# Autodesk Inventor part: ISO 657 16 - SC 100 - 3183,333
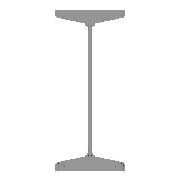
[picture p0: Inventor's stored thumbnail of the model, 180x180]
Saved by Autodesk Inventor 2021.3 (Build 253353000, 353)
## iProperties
IsCustomPart: 1
_CCFamilyMember: 1
_CCFamilyDisplayName: ISO 657/16 - 1980 - Poutres en acier laminées à chaud - Partie 16: profilés en H (série métrique) - Cotes et propriétés de section
_FrameMemberDoc: Frame Member File
_Version: 25.0.0
_GetPNFromCC: 1
Created: 2018-07
Part Number: ISO 657 16 - SC 100 - 3183,333
Material: Acier, doux
Description: Poutres en acier laminées à chaud - Partie 16: profilés en H (série métrique) - Cotes et propriétés de section
Document SubType Name: Modeling
Standard: ISO
Designer: Fabian Perrée
Standard Revision: First edition 1980-02-15
Standards Organization: ISO
Language: fr-FR
Size Designation: SC 100
Categories: <MemberInstance><Categories><Category DisplayName="Profilés" InternalName="089c4875-fa83-4c05-b084-43b9cc11f5ed" Mnemonic="GRDR"><CategoryParameter DisplayName=
Stock Number: SC 100
Density: 7.85 g/cm^3
Appearance: Semi-poli
Mass: 62799.5 g
Surface Area: 17060.8 cm^2
Volume: 7999.94 cm^3
G_W: 100,000 mm
G_H: 100,000 mm
+C8570A6E-3ADF-402B-AF4B-F69D73FB0D4A+DETAILDECOUPE1: Angle de coupe 67,38 deg
+12B5BAF0-3E22-4404-8C3D-A4FF2A8CEEA4+DETAILDECOUPE2: Angle de coupe 67,38 deg
G_L: 3183,333 mm
Author: Fabian Perrée
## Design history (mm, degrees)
node "Plan de départ"
node "Plan de fin"
sketch "Esquisse"
  geometry: L1 (-3, 0)-(-3, -26.266); L2 (-13.33, -38.149)-(-44.835, -42.577); L3 (-50, -48.518)-(-50, -50); L4 (-50, -50)-(0, -50); L5 (-26.5, -50)-(-26.5, -40); L6 (-61.333, 0)-(81.777, 0); L7 (0, 0)-(0, -50); L8 (0, -60)-(0, 80); L9 (3, 0)-(3, -26.266); L10 (13.33, -38.149)-(44.835, -42.577); L11 (50, -48.518)-(50, -50); L12 (50, -50)-(0, -50); L13 (-3, 0)-(0, 0); L14 (-3, 0)-(-3, 26.266); L15 (-13.33, 38.149)-(-44.835, 42.577); L16 (-50, 48.518)-(-50, 50); L17 (-50, 50)-(0, 50); L18 (50, 48.518)-(50, 50); L19 (13.33, 38.149)-(44.835, 42.577); L20 (3, 0)-(3, 26.266); L21 (50, 50)-(0, 50); L22 (0, 108)-(0, -88) reference; L23 (-89.955, 0)-(110.399, 0) reference; A1 r 6 centre (-44, 48.518) between (-50, 48.518) and (-44.835, 42.577); A2 r 6 centre (44, 48.518) between (44.835, 42.577) and (50, 48.518); A3 r 6 centre (44, -48.518) between (50, -48.518) and (44.835, -42.577); A4 r 6 centre (-44, -48.518) between (-44.835, -42.577) and (-50, -48.518); A5 r 12 centre (-15, 26.266) between (-3, 26.266) and (-13.33, 38.149); A6 r 12 centre (15, 26.266) between (13.33, 38.149) and (3, 26.266); A7 r 12 centre (15, -26.266) between (3, -26.266) and (13.33, -38.149); A8 r 12 centre (-15, -26.266) between (-13.33, -38.149) and (-3, -26.266); 14 further points
  constraints: 42 end point, 24 point on line, 17 symmetric about line, 16 point on circle, 16 tangent, 8 centre point, 6 equal radius, 4 collinear, 2 perpendicular, 12 other
  dimensions: "d1" = 10 vertical distance of L3.end L5.end (= G_T1); "d2" = 23.5 distance between parallel lines of L5 L3 (= -0.25 x G_T + 0.25 x G_W); "d3" = 3 distance between parallel lines of L1 L7 (= 0.5 x G_T); "d4" = 50 distance between parallel lines of L7 L3 (= 0.5 x G_W); "d9" = 50 distance from line of L1.start L4 (= 0.5 x G_H); "d14" = 98 deg angle of L2 L1 (= G_NG); "d15" = 6 radius of A1 (= G_ER); "d16" = 12 radius of A5 (= G_IR)
extrude "Corps" new body sketch "Esquisse" stored distance "d5" = 3183.33333 (= G_L); taper "d6" = 0 deg
node "Driven Length"
  sketch "Sketch3"
    geometry: L1 (0, 0)-(10, 0) reference
    constraints: 2 end point, 1 horizontal
  workplane "Work Plane3"
  sketch "Sketch4"
    geometry: L1 (-2, 0)-(12, 0) reference; L2 (-2, 3183.333)-(12, 3183.333) reference
    dimensions: "d20" = 3183.33333 distance between parallel lines of L1 L2 (derived)
node "Plan de construction4"
feature "Scission1"
node "Plan de construction5"
feature "Scission2"
body "Solid1"
other parameters: "G_W" = 100 (= G_H) [user parameter; used in 2 equation terms], "G_H" = 100 [user parameter; used in 2 equation terms], "G_T" = 6 [user parameter; used in 2 equation terms], "G_T1" = 10 [user parameter; used in 1 equation term], "G_L" = 3183.33333 (= d20) [user parameter; used in 1 equation term], "G_ER" = 6 [user parameter; used in 1 equation term], "G_IR" = 12 [user parameter; used in 1 equation term], "G_NG" = 98 deg [user parameter; used in 1 equation term], "G_OFFSET_START" = 0 [user parameter; used in 1 equation term], "G_OFFSET_END" = -66.66667 [user parameter; used in 1 equation term], "d17" = 0 (computed from G_OFFSET_START), "d18" = 3183.33333 (= G_OFFSET_END + B_L), "d19" = 90 deg
